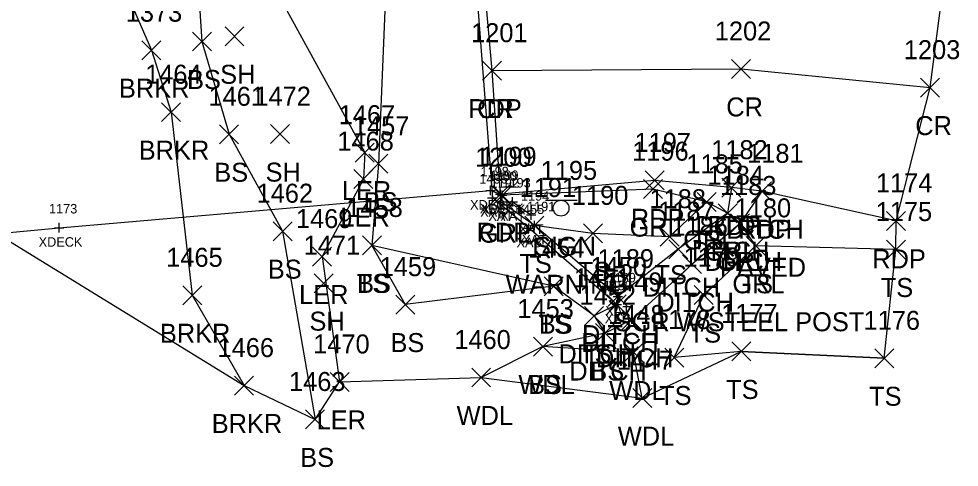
# Model space of a CAD drawing. Extents: x 1505684 to 1510253, y 730355 to 731397.
# Drawn here: x 1510141.5 to 1510240.6, y 730871.2 to 730918.5 of the extents above; entities that cross this region are included whole.
import ezdxf

# ---------------------------------------------------------------- set-up
doc = ezdxf.new("R2010")
doc.units = 0
for name, color, linetype in [('B_A', 7, 'Continuous'), ('B_I', 7, 'Continuous'), ('B_TIC', 7, 'Continuous'), ('BELB', 7, 'Continuous'), ('BSUBM', 7, 'Continuous'), ('D_A', 7, 'Continuous'), ('D_I', 7, 'Continuous'), ('D_TIC', 7, 'Continuous'), ('DD', 7, 'Continuous'), ('L_A', 7, 'Continuous'), ('L_I', 7, 'Continuous'), ('L_TIC', 7, 'Continuous'), ('LARO', 7, 'Continuous'), ('LAWA', 7, 'Continuous'), ('LAWE', 7, 'Continuous'), ('LELB', 7, 'Continuous'), ('LSOGP', 7, 'Continuous'), ('P_A', 7, 'Continuous'), ('P_C', 7, 'Continuous'), ('P_I', 7, 'Continuous'), ('P_TIC', 7, 'Continuous'), ('PET', 7, 'Continuous'), ('PRC', 7, 'Continuous'), ('R_A', 7, 'Continuous'), ('R_C', 7, 'Continuous'), ('R_I', 7, 'Continuous'), ('R_TIC', 7, 'Continuous'), ('RGR', 7, 'Continuous'), ('S_A', 7, 'Continuous'), ('S_C', 7, 'Continuous'), ('S_I', 7, 'Continuous'), ('SSGN', 7, 'Continuous')]:
    doc.layers.add(name, color=color, linetype=linetype)

msp = doc.modelspace()

# ---------------------------------------------------------------- linework, layer by layer
at = {"layer": 'B_TIC'}
for p, q in [((1510191.188, 730900.384), (1510191.263, 730900.384)), ((1510191.375, 730899.62), (1510191.451, 730899.62)), ((1510191.375, 730899.62), (1510191.451, 730899.62)), ((1510192.221, 730899.998), (1510192.296, 730899.998)), ((1510192.412, 730899.895), (1510192.488, 730899.895)), ((1510192.257, 730899.18), (1510192.333, 730899.18)), ((1510193.507, 730899.205), (1510193.583, 730899.205)), ((1510195.459, 730897.817), (1510195.534, 730897.817)), ((1510145.728, 730896.473), (1510145.803, 730896.473)), ((1510195.208, 730896.411), (1510195.284, 730896.411)), ((1510195.808, 730896.703), (1510195.883, 730896.703)), ((1510204.489, 730888.383), (1510204.565, 730888.383)), ((1510204.591, 730889.209), (1510204.666, 730889.209))]:
    msp.add_line(p, q, dxfattribs=at)
for points in [[(1510190.684, 730900.384), (1510191.684, 730900.384)], [(1510191.184, 730899.884), (1510191.184, 730900.884)], [(1510192.217, 730899.498), (1510192.217, 730900.498)], [(1510192.409, 730899.395), (1510192.409, 730900.395)], [(1510190.872, 730899.62), (1510191.872, 730899.62)], [(1510190.872, 730899.62), (1510191.872, 730899.62)], [(1510191.372, 730899.12), (1510191.372, 730900.12)], [(1510191.372, 730899.12), (1510191.372, 730900.12)], [(1510191.717, 730899.998), (1510192.717, 730899.998)], [(1510191.909, 730899.895), (1510192.909, 730899.895)], [(1510192.254, 730898.68), (1510192.254, 730899.68)], [(1510193.504, 730898.705), (1510193.504, 730899.705)], [(1510191.754, 730899.18), (1510192.754, 730899.18)], [(1510193.004, 730899.205), (1510194.004, 730899.205)], [(1510195.455, 730897.317), (1510195.455, 730898.317)], [(1510194.955, 730897.817), (1510195.955, 730897.817)], [(1510145.224, 730896.473), (1510146.224, 730896.473)], [(1510145.724, 730895.973), (1510145.724, 730896.973)], [(1510194.705, 730896.411), (1510195.705, 730896.411)], [(1510195.205, 730895.911), (1510195.205, 730896.911)], [(1510195.304, 730896.703), (1510196.304, 730896.703)], [(1510195.804, 730896.203), (1510195.804, 730897.203)], [(1510204.587, 730888.709), (1510204.587, 730889.709)], [(1510203.986, 730888.383), (1510204.986, 730888.383)], [(1510204.087, 730889.209), (1510205.087, 730889.209)], [(1510204.486, 730887.883), (1510204.486, 730888.883)]]:
    msp.add_lwpolyline(points, dxfattribs=at)
at = {"layer": 'BELB'}
msp.add_lwpolyline([(1510099.175, 730891.61), (1510099.525, 730892.156), (1510145.724, 730896.473), (1510191.184, 730900.384), (1510192.217, 730899.998), (1510192.409, 730899.895)], dxfattribs=at)
at = {"layer": 'BSUBM'}
for points in [[(1510188.784, 730931.125), (1510189.165, 730929.104), (1510189.122, 730928.98), (1510189.306, 730926.835), (1510189.323, 730926.535), (1510191.372, 730899.62)], [(1510204.486, 730888.383), (1510195.205, 730896.411), (1510191.372, 730899.62)], [(1510204.587, 730889.209), (1510195.804, 730896.703), (1510192.254, 730899.18), (1510193.504, 730899.205), (1510195.455, 730897.817)]]:
    msp.add_lwpolyline(points, dxfattribs=at)
at = {"layer": 'D_TIC'}
for points in [[(1510215.555, 730899.691), (1510217.555, 730901.691)], [(1510217.555, 730899.691), (1510215.555, 730901.691)], [(1510218.776, 730899.306), (1510220.776, 730901.306)], [(1510220.776, 730899.306), (1510218.776, 730901.306)], [(1510215.165, 730896.994), (1510217.165, 730898.994)], [(1510217.165, 730896.994), (1510215.165, 730898.994)], [(1510216.481, 730895.92), (1510218.481, 730897.92)], [(1510218.481, 730895.92), (1510216.481, 730897.92)], [(1510209.967, 730893.209), (1510211.967, 730895.209)], [(1510211.967, 730893.209), (1510209.967, 730895.209)], [(1510211.419, 730891.63), (1510213.419, 730893.63)], [(1510213.419, 730891.63), (1510211.419, 730893.63)], [(1510203.486, 730887.383), (1510205.486, 730889.383)], [(1510205.486, 730887.383), (1510203.486, 730889.383)], [(1510203.587, 730888.209), (1510205.587, 730890.209)], [(1510205.587, 730888.209), (1510203.587, 730890.209)], [(1510201.098, 730886.185), (1510203.098, 730888.185)], [(1510203.098, 730886.185), (1510201.098, 730888.185)], [(1510205.046, 730885.763), (1510207.046, 730887.763)], [(1510207.046, 730885.763), (1510205.046, 730887.763)], [(1510202.248, 730884.375), (1510204.248, 730886.375)], [(1510204.248, 730884.375), (1510202.248, 730886.375)], [(1510202.248, 730884.375), (1510204.248, 730886.375)], [(1510204.248, 730884.375), (1510202.248, 730886.375)]]:
    msp.add_lwpolyline(points, dxfattribs=at)
at = {"layer": 'DD'}
for points in [[(1510216.555, 730900.691), (1510216.165, 730897.994), (1510210.967, 730894.209), (1510204.587, 730889.209), (1510204.486, 730888.383), (1510202.098, 730887.185), (1510203.248, 730885.375)], [(1510219.776, 730900.306), (1510217.481, 730896.92), (1510212.419, 730892.63), (1510206.046, 730886.763), (1510203.248, 730885.375)]]:
    msp.add_lwpolyline(points, dxfattribs=at)
at = {"layer": 'L_TIC'}
for points in [[(1510159.762, 730915.086), (1510161.762, 730917.086)], [(1510161.762, 730915.086), (1510159.762, 730917.086)], [(1510163.203, 730915.634), (1510165.203, 730917.634)], [(1510165.203, 730915.634), (1510163.203, 730917.634)], [(1510154.439, 730914.171), (1510156.439, 730916.171)], [(1510156.439, 730914.171), (1510154.439, 730916.171)], [(1510156.525, 730907.642), (1510158.525, 730909.642)], [(1510158.525, 730907.642), (1510156.525, 730909.642)], [(1510162.632, 730905.312), (1510164.632, 730907.312)], [(1510164.632, 730905.312), (1510162.632, 730907.312)], [(1510167.987, 730905.326), (1510169.987, 730907.326)], [(1510169.987, 730905.326), (1510167.987, 730907.326)], [(1510176.92, 730903.378), (1510178.92, 730905.378)], [(1510178.92, 730903.378), (1510176.92, 730905.378)], [(1510178.372, 730902.209), (1510180.372, 730904.209)], [(1510180.372, 730902.209), (1510178.372, 730904.209)], [(1510176.778, 730900.597), (1510178.778, 730902.597)], [(1510178.778, 730900.597), (1510176.778, 730902.597)], [(1510212.941, 730898.19), (1510214.941, 730900.19)], [(1510214.941, 730898.19), (1510212.941, 730900.19)], [(1510194.804, 730895.703), (1510196.804, 730897.703)], [(1510196.804, 730895.703), (1510194.804, 730897.703)], [(1510168.271, 730895.105), (1510170.271, 730897.105)], [(1510170.271, 730895.105), (1510168.271, 730897.105)], [(1510200.965, 730894.876), (1510202.965, 730896.876)], [(1510202.965, 730894.876), (1510200.965, 730896.876)], [(1510209.051, 730894.526), (1510211.051, 730896.526)], [(1510211.051, 730894.526), (1510209.051, 730896.526)], [(1510177.676, 730893.605), (1510179.676, 730895.605)], [(1510179.676, 730893.605), (1510177.676, 730895.605)], [(1510177.676, 730893.605), (1510179.676, 730895.605)], [(1510179.676, 730893.605), (1510177.676, 730895.605)], [(1510218.12, 730893.562), (1510220.12, 730895.562)], [(1510220.12, 730893.562), (1510218.12, 730895.562)], [(1510218.12, 730893.562), (1510220.12, 730895.562)], [(1510220.12, 730893.562), (1510218.12, 730895.562)], [(1510172.423, 730892.43), (1510174.423, 730894.43)], [(1510174.423, 730892.43), (1510172.423, 730894.43)], [(1510232.888, 730893.171), (1510234.888, 730895.171)], [(1510234.888, 730893.171), (1510232.888, 730895.171)], [(1510172.612, 730889.626), (1510174.612, 730891.626)], [(1510174.612, 730889.626), (1510172.612, 730891.626)], [(1510158.748, 730888.351), (1510160.748, 730890.351)], [(1510160.748, 730888.351), (1510158.748, 730890.351)], [(1510196.822, 730889.311), (1510198.822, 730891.311)], [(1510198.822, 730889.311), (1510196.822, 730891.311)], [(1510196.822, 730889.311), (1510198.822, 730891.311)], [(1510198.822, 730889.311), (1510196.822, 730891.311)], [(1510212.646, 730888.366), (1510214.646, 730890.366)], [(1510214.646, 730888.366), (1510212.646, 730890.366)], [(1510181.197, 730887.37), (1510183.197, 730889.37)], [(1510183.197, 730887.37), (1510181.197, 730889.37)], [(1510181.197, 730887.37), (1510183.197, 730889.37)], [(1510183.197, 730887.37), (1510181.197, 730889.37)], [(1510201.098, 730886.185), (1510203.098, 730888.185)], [(1510203.098, 730886.185), (1510201.098, 730888.185)], [(1510202.248, 730884.375), (1510204.248, 730886.375)], [(1510204.248, 730884.375), (1510202.248, 730886.375)], [(1510195.699, 730882.95), (1510197.699, 730884.95)], [(1510197.699, 730882.95), (1510195.699, 730884.95)], [(1510195.699, 730882.95), (1510197.699, 730884.95)], [(1510197.699, 730882.95), (1510195.699, 730884.95)], [(1510216.602, 730882.432), (1510218.602, 730884.432)], [(1510218.602, 730882.432), (1510216.602, 730884.432)], [(1510205.26, 730882.326), (1510207.26, 730884.326)], [(1510207.26, 730882.326), (1510205.26, 730884.326)], [(1510209.534, 730881.794), (1510211.534, 730883.794)], [(1510211.534, 730881.794), (1510209.534, 730883.794)], [(1510231.662, 730881.714), (1510233.662, 730883.714)], [(1510233.662, 730881.714), (1510231.662, 730883.714)], [(1510189.192, 730879.691), (1510191.192, 730881.691)], [(1510191.192, 730879.691), (1510189.192, 730881.691)], [(1510164.212, 730878.843), (1510166.212, 730880.843)], [(1510166.212, 730878.843), (1510164.212, 730880.843)], [(1510174.272, 730879.225), (1510176.272, 730881.225)], [(1510176.272, 730879.225), (1510174.272, 730881.225)], [(1510206.173, 730877.517), (1510208.173, 730879.517)], [(1510208.173, 730877.517), (1510206.173, 730879.517)], [(1510171.686, 730875.272), (1510173.686, 730877.272)], [(1510173.686, 730875.272), (1510171.686, 730877.272)]]:
    msp.add_lwpolyline(points, dxfattribs=at)
at = {"layer": 'LARO'}
msp.add_lwpolyline([(1510165.194, 730929.39), (1510165.596, 730926.859), (1510177.92, 730904.378), (1510177.778, 730901.597), (1510173.423, 730893.43), (1510175.272, 730880.225)], dxfattribs=at)
at = {"layer": 'LAWA'}
msp.add_lwpolyline([(1510207.173, 730878.517), (1510206.26, 730883.326), (1510196.699, 730883.95), (1510190.192, 730880.691)], dxfattribs=at)
at = {"layer": 'LAWE'}
msp.add_lwpolyline([(1510147.562, 730990.156), (1510149.891, 730976.157), (1510148.239, 730964.543), (1510148.587, 730950.317), (1510150.043, 730940.021), (1510154.699, 730931.705), (1510151.716, 730923.73), (1510155.439, 730915.171), (1510157.525, 730908.642), (1510159.748, 730889.351), (1510165.212, 730879.843)], dxfattribs=at)
at = {"layer": 'LELB'}
for points in [[(1510151.004, 730976.626), (1510156.58, 730971.051), (1510156.251, 730960.212), (1510154.169, 730951.632), (1510155.837, 730946.251), (1510157.72, 730937.242), (1510159.355, 730928.387), (1510160.052, 730926.869), (1510160.762, 730916.086), (1510163.632, 730906.312), (1510169.271, 730896.105), (1510172.686, 730876.272)], [(1510180.502, 730930.404), (1510179.372, 730903.209), (1510178.676, 730894.605), (1510182.197, 730888.37)], [(1510213.941, 730899.19), (1510210.051, 730895.526), (1510201.965, 730895.876), (1510195.804, 730896.703)], [(1510202.098, 730887.185), (1510197.822, 730890.311), (1510178.676, 730894.605)], [(1510232.662, 730882.714), (1510217.602, 730883.432), (1510210.534, 730882.794), (1510213.646, 730889.366), (1510219.12, 730894.562)], [(1510233.888, 730894.171), (1510219.12, 730894.562)], [(1510197.822, 730890.311), (1510182.197, 730888.37)], [(1510203.248, 730885.375), (1510196.699, 730883.95)]]:
    msp.add_lwpolyline(points, dxfattribs=at)
at = {"layer": 'LSOGP'}
msp.add_lwpolyline([(1510135.81, 730897.892), (1510165.212, 730879.843), (1510172.686, 730876.272), (1510175.272, 730880.225), (1510190.192, 730880.691), (1510207.173, 730878.517), (1510217.602, 730883.432), (1510232.662, 730882.714), (1510233.888, 730894.171), (1510233.913, 730897.188), (1510237.501, 730911.225), (1510239.574, 730927.207)], dxfattribs=at)
at = {"layer": 'P_TIC'}
for points in [[(1510216.586, 730912.193), (1510218.586, 730914.193)], [(1510218.586, 730912.193), (1510216.586, 730914.193)], [(1510190.338, 730912.015), (1510192.338, 730914.015)], [(1510192.338, 730912.015), (1510190.338, 730914.015)], [(1510190.338, 730912.015), (1510192.338, 730914.015)], [(1510192.338, 730912.015), (1510190.338, 730914.015)], [(1510236.501, 730910.225), (1510238.501, 730912.225)], [(1510238.501, 730910.225), (1510236.501, 730912.225)], [(1510207.471, 730900.46), (1510209.471, 730902.46)], [(1510209.471, 730900.46), (1510207.471, 730902.46)], [(1510215.555, 730899.691), (1510217.555, 730901.691)], [(1510217.555, 730899.691), (1510215.555, 730901.691)], [(1510218.776, 730899.306), (1510220.776, 730901.306)], [(1510220.776, 730899.306), (1510218.776, 730901.306)], [(1510191.217, 730898.998), (1510193.217, 730900.998)], [(1510193.217, 730898.998), (1510191.217, 730900.998)], [(1510232.913, 730896.188), (1510234.913, 730898.188)], [(1510234.913, 730896.188), (1510232.913, 730898.188)]]:
    msp.add_lwpolyline(points, dxfattribs=at)
at = {"layer": 'PET'}
msp.add_lwpolyline([(1510233.913, 730897.188), (1510219.776, 730900.306), (1510216.555, 730900.691), (1510208.471, 730901.46), (1510192.217, 730899.998), (1510191.338, 730913.015), (1510189.909, 730929.156), (1510222.998, 730928.933), (1510239.574, 730927.207)], dxfattribs=at)
at = {"layer": 'PRC'}
msp.add_lwpolyline([(1510191.338, 730913.015), (1510217.586, 730913.193), (1510237.501, 730911.225)], dxfattribs=at)
at = {"layer": 'R_TIC'}
for points in [[(1510207.285, 730899.533), (1510209.285, 730901.533)], [(1510209.285, 730899.533), (1510207.285, 730901.533)], [(1510191.409, 730898.895), (1510193.409, 730900.895)], [(1510193.409, 730898.895), (1510191.409, 730900.895)], [(1510212.941, 730898.19), (1510214.941, 730900.19)], [(1510214.941, 730898.19), (1510212.941, 730900.19)], [(1510215.165, 730896.994), (1510217.165, 730898.994)], [(1510217.165, 730896.994), (1510215.165, 730898.994)], [(1510216.481, 730895.92), (1510218.481, 730897.92)], [(1510218.481, 730895.92), (1510216.481, 730897.92)], [(1510218.12, 730893.562), (1510220.12, 730895.562)], [(1510220.12, 730893.562), (1510218.12, 730895.562)]]:
    msp.add_lwpolyline(points, dxfattribs=at)
at = {"layer": 'RGR'}
msp.add_lwpolyline([(1510219.12, 730894.562), (1510217.481, 730896.92), (1510216.165, 730897.994), (1510213.941, 730899.19), (1510208.285, 730900.533), (1510192.409, 730899.895)], dxfattribs=at)
at = {"layer": 'SSGN'}
for p, q in [((1510196.965, 730899.364), (1510200.298, 730899.364)), ((1510198.611, 730898.531), (1510198.611, 730898.531))]:
    msp.add_line(p, q, dxfattribs=at)
msp.add_circle((1510198.611, 730898.531), 0.833, dxfattribs=at)

# ---------------------------------------------------------------- texts
at = {"layer": 'B_A'}
for s, p in [('XDECK', (1510189.027, 730898.384)), ('XDECK', (1510190.06, 730897.998)), ('XAB', (1510190.092, 730897.62)), ('XAB', (1510190.092, 730897.62)), ('XDECK', (1510190.251, 730897.895)), ('XAT', (1510190.958, 730897.18)), ('XAT', (1510192.209, 730897.205)), ('XAT', (1510194.16, 730895.817)), ('XDECK', (1510143.567, 730894.473)), ('XAB', (1510193.925, 730894.411)), ('XAT', (1510194.509, 730894.703)), ('XAB', (1510203.206, 730886.383)), ('XAT', (1510203.292, 730887.209))]:
    msp.add_text(s, height=1, dxfattribs=at).set_placement(p)
at = {"layer": 'B_I'}
for s, p in [('1198', (1510190.121, 730901.884)), ('1200', (1510190.979, 730901.395)), ('1199', (1510191.151, 730901.498)), ('1456', (1510189.998, 730901.12)), ('1456', (1510189.998, 730901.12)), ('1192', (1510191.191, 730900.68)), ('1193', (1510192.441, 730900.705)), ('1194', (1510194.392, 730899.317)), ('1173', (1510144.661, 730897.973)), ('1455', (1510193.858, 730897.911)), ('1191', (1510195.025, 730898.203)), ('1189', (1510203.52, 730890.709)), ('1450', (1510203.096, 730889.883))]:
    msp.add_text(s, height=1, dxfattribs=at).set_placement(p)
at = {"layer": 'D_A'}
for p in [(1510212.791, 730895.691), (1510216.013, 730895.306), (1510212.401, 730892.994), (1510213.718, 730891.92), (1510207.203, 730889.209), (1510208.655, 730887.63), (1510200.722, 730883.383), (1510200.824, 730884.209), (1510198.334, 730882.185), (1510202.282, 730881.763), (1510199.484, 730880.375), (1510199.484, 730880.375)]:
    msp.add_text('DITCH', height=2, dxfattribs=at).set_placement(p)
at = {"layer": 'D_I'}
for s, p in [('1182', (1510214.429, 730903.691)), ('1181', (1510218.217, 730903.306)), ('1184', (1510214.039, 730900.994)), ('1183', (1510215.355, 730899.92)), ('1187', (1510208.841, 730897.209)), ('1186', (1510210.238, 730895.63)), ('1450', (1510201.706, 730891.383)), ('1189', (1510202.453, 730892.209)), ('1451', (1510199.972, 730890.185)), ('1449', (1510203.345, 730889.763)), ('1452', (1510200.555, 730888.375)), ('1452', (1510200.555, 730888.375))]:
    msp.add_text(s, height=2, dxfattribs=at).set_placement(p)
at = {"layer": 'L_A'}
for s, p in [('BS', (1510159.203, 730911.086)), ('SH', (1510162.691, 730911.634)), ('BRKR', (1510152.029, 730910.171)), ('BRKR', (1510154.116, 730903.642)), ('BS', (1510162.073, 730901.312)), ('SH', (1510167.475, 730901.326)), ('LER', (1510175.503, 730899.378)), ('BS', (1510177.813, 730898.209)), ('LER', (1510175.361, 730896.597)), ('TS', (1510212.351, 730894.19)), ('TS', (1510194.214, 730891.703)), ('BS', (1510167.712, 730891.105)), ('TS', (1510200.374, 730890.876)), ('TS', (1510208.46, 730890.526)), ('TS', (1510177.086, 730889.605)), ('BS', (1510177.117, 730889.605)), ('TS', (1510217.529, 730889.562)), ('TS', (1510217.529, 730889.562)), ('LER', (1510171.006, 730888.43)), ('TS', (1510232.297, 730889.171)), ('SH', (1510172.1, 730885.626)), ('TS', (1510196.231, 730885.311)), ('BS', (1510196.263, 730885.311)), ('TS', (1510212.055, 730884.366)), ('BRKR', (1510156.339, 730884.351)), ('BS', (1510180.638, 730883.37)), ('BS', (1510180.638, 730883.37)), ('TS', (1510200.508, 730882.185)), ('BS', (1510201.689, 730880.375)), ('WDL', (1510194.116, 730878.95)), ('BS', (1510195.14, 730878.95)), ('TS', (1510216.011, 730878.432)), ('WDL', (1510203.677, 730878.326)), ('TS', (1510208.943, 730877.794)), ('TS', (1510231.072, 730877.714)), ('WDL', (1510187.609, 730875.691)), ('BRKR', (1510161.803, 730874.843)), ('LER', (1510172.855, 730875.225)), ('WDL', (1510204.59, 730873.517)), ('BS', (1510171.127, 730871.272))]:
    msp.add_text(s, height=2, dxfattribs=at).set_placement(p)
at = {"layer": 'L_I'}
for s, p in [('1373', (1510152.746, 730918.171)), ('1464', (1510154.785, 730911.642)), ('1461', (1510161.459, 730909.312)), ('1472', (1510166.294, 730909.326)), ('1467', (1510175.18, 730907.378)), ('1457', (1510176.679, 730906.209)), ('1468', (1510175.038, 730904.597)), ('1185', (1510211.816, 730902.19)), ('1191', (1510194.245, 730899.703)), ('1462', (1510166.531, 730899.105)), ('1190', (1510199.752, 730898.876)), ('1188', (1510207.925, 730898.526)), ('1458', (1510175.984, 730897.605)), ('1458', (1510175.984, 730897.605)), ('1180', (1510216.907, 730897.562)), ('1180', (1510216.907, 730897.562)), ('1469', (1510170.675, 730896.43)), ('1175', (1510231.762, 730897.171)), ('1471', (1510171.486, 730893.626)), ('1454', (1510195.129, 730893.311)), ('1454', (1510195.129, 730893.311)), ('1465', (1510157.008, 730892.351)), ('1179', (1510211.512, 730892.366)), ('1459', (1510179.496, 730891.37)), ('1459', (1510179.496, 730891.37)), ('1451', (1510199.972, 730890.185)), ('1452', (1510200.555, 730888.375)), ('1453', (1510194.006, 730886.95)), ('1453', (1510194.006, 730886.95)), ('1448', (1510203.567, 730886.326)), ('1177', (1510215.476, 730886.432)), ('1178', (1510208.408, 730885.794)), ('1176', (1510230.481, 730885.714)), ('1460', (1510187.365, 730883.691)), ('1466', (1510162.417, 730882.843)), ('1470', (1510172.493, 730883.225)), ('1447', (1510204.48, 730881.517)), ('1463', (1510169.946, 730879.272))]:
    msp.add_text(s, height=2, dxfattribs=at).set_placement(p)
at = {"layer": 'P_A'}
for s, p in [('CR', (1510216.019, 730908.193)), ('RDP', (1510188.826, 730908.015)), ('CR', (1510189.771, 730908.015)), ('CR', (1510235.934, 730906.225)), ('RDP', (1510205.959, 730896.46)), ('RDP', (1510214.043, 730895.691)), ('RDP', (1510217.265, 730895.306)), ('RDP', (1510189.706, 730894.998)), ('RDP', (1510231.401, 730892.188))]:
    msp.add_text(s, height=2, dxfattribs=at).set_placement(p)
at = {"layer": 'P_C'}
msp.add_text('PAVED', height=2, dxfattribs=at).set_placement((1510215.359, 730891.306))
at = {"layer": 'P_I'}
for s, p in [('1202', (1510214.814, 730916.193)), ('1201', (1510189.133, 730916.015)), ('1201', (1510189.133, 730916.015)), ('1203', (1510234.73, 730914.225)), ('1197', (1510206.345, 730904.46)), ('1182', (1510214.429, 730903.691)), ('1181', (1510218.217, 730903.306)), ('1199', (1510190.084, 730902.998)), ('1174', (1510231.787, 730900.188))]:
    msp.add_text(s, height=2, dxfattribs=at).set_placement(p)
at = {"layer": 'R_A'}
for p in [(1510205.828, 730895.533), (1510189.952, 730894.895), (1510211.485, 730894.19), (1510213.708, 730892.994), (1510215.025, 730891.92), (1510216.663, 730889.562)]:
    msp.add_text('GRL', height=2, dxfattribs=at).set_placement(p)
at = {"layer": 'R_C'}
msp.add_text('SGR W/STEEL POST', height=2, dxfattribs=at).set_placement((1510204.261, 730885.562))
at = {"layer": 'R_I'}
for s, p in [('1196', (1510206.104, 730903.533)), ('1200', (1510189.55, 730902.895)), ('1185', (1510211.816, 730902.19)), ('1184', (1510214.039, 730900.994)), ('1183', (1510215.355, 730899.92)), ('1180', (1510216.907, 730897.562))]:
    msp.add_text(s, height=2, dxfattribs=at).set_placement(p)
at = {"layer": 'S_A'}
msp.add_text('SIGN', height=2, dxfattribs=at).set_placement((1510195.749, 730893.51))
at = {"layer": 'S_C'}
msp.add_text('WARNING', height=2, dxfattribs=at).set_placement((1510192.757, 730889.51))
at = {"layer": 'S_I'}
msp.add_text('1195', height=2, dxfattribs=at).set_placement((1510196.466, 730901.51))

doc.saveas('drawing.dxf')
